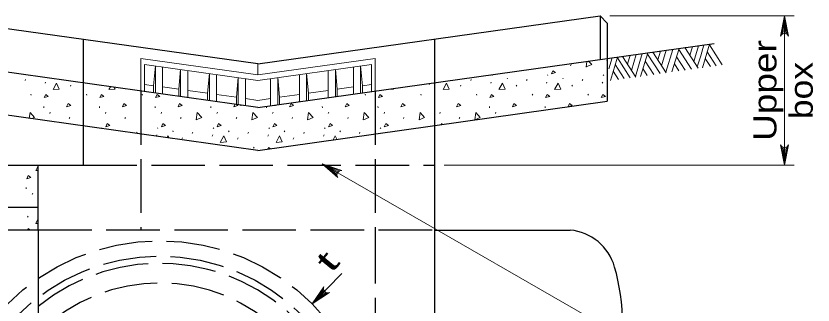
# Model space of a CAD drawing. Extents: x 1073.4 to 1107.4, y 719.4 to 741.4.
# Drawn here: x 1078.83 to 1084.36, y 727.47 to 729.48 of the extents above; entities that cross this region are included whole.
import ezdxf
from ezdxf.enums import TextEntityAlignment as Align

# ---------------------------------------------------------------- set-up
doc = ezdxf.new("R2010")
doc.units = 0
doc.header["$LTSCALE"] = 0.062
doc.linetypes.add('LONG_DASHED', pattern=[7.5, 6, -1.5])
doc.layers.add('1', color=7, linetype='Continuous', lineweight=13)

msp = doc.modelspace()

# ---------------------------------------------------------------- linework, layer by layer
at = {"layer": '1', "lineweight": 25}
for p, q in [((1080.51042, 729.14492), (1078.149, 729.47683)), ((1080.51042, 729.14492), (1082.88425, 729.47858)), ((1082.93425, 729.42867), (1082.88425, 729.47858)), ((1082.88425, 729.47858), (1082.88425, 729.17583)), ((1082.93425, 729.42867), (1082.93425, 728.88592)), ((1081.73483, 729.317), (1081.73483, 729.01425)), ((1079.29842, 729.31525), (1079.29842, 729.0125)), ((1082.93425, 729.18283), (1083.67667, 729.28717)), ((1080.51042, 728.84217), (1078.0865, 729.18283)), ((1080.51042, 728.84217), (1082.93425, 729.18283)), ((1080.51042, 728.54525), (1078.0865, 728.88592)), ((1080.51042, 728.54525), (1082.93425, 728.88592)), ((1079.29842, 728.71567), (1079.29842, 728.4425)), ((1081.73483, 728.71742), (1081.73483, 723.54533)), ((1077.93658, 728.4425), (1078.98608, 728.4425)), ((1078.98608, 728.4425), (1079.29842, 728.4425)), ((1078.98608, 727.99275), (1078.98608, 728.4425)), ((1078.10517, 728.15183), (1078.98483, 728.15183)), ((1077.93658, 727.99275), (1078.98608, 727.99275)), ((1078.98608, 727.99275), (1078.98608, 724.04508)), ((1081.73483, 727.99225), (1082.67692, 727.99225))]:
    msp.add_line(p, q, dxfattribs=at)
at = {"layer": '1'}
for p, q in [((1082.95092, 729.47858), (1084.231, 729.47858)), ((1084.1445, 729.34883), (1084.16433, 729.47858)), ((1084.15283, 729.35375), (1084.16433, 729.47858)), ((1084.16433, 729.47858), (1084.16433, 728.4425)), ((1084.16433, 729.35608), (1084.16433, 729.47858)), ((1084.17342, 729.35475), (1084.16433, 729.47858)), ((1084.18225, 729.35042), (1084.16433, 729.47858)), ((1083.50717, 729.20367), (1083.52558, 729.26592)), ((1083.53392, 729.16233), (1083.5675, 729.27183)), ((1083.58217, 729.20108), (1083.605, 729.27708)), ((1083.59375, 729.11925), (1083.64308, 729.28242)), ((1083.73175, 729.13875), (1083.64242, 729.2775)), ((1083.10208, 729.10008), (1083.13542, 729.21108)), ((1083.12883, 729.05875), (1083.17692, 729.21692)), ((1083.16408, 729.05892), (1083.21442, 729.22217)), ((1083.30017, 729.07808), (1083.21217, 729.21408)), ((1083.34258, 729.084), (1083.25025, 729.22708)), ((1083.28533, 729.17442), (1083.303, 729.23467)), ((1083.31142, 729.1325), (1083.34383, 729.24042)), ((1083.34, 729.088), (1083.38808, 729.24658)), ((1083.38258, 729.08958), (1083.43242, 729.25283)), ((1083.51858, 729.10875), (1083.43008, 729.24517)), ((1083.56433, 729.11508), (1083.47183, 729.25842)), ((1083.68992, 729.13275), (1083.62767, 729.23017)), ((1079.69825, 729.18342), (1079.69825, 728.95633)), ((1079.69825, 729.18342), (1080.51042, 729.06925)), ((1081.3225, 729.18342), (1080.51042, 729.06925)), ((1081.3225, 729.18342), (1081.3225, 728.95633)), ((1082.78758, 729.12383), (1082.793, 729.163)), ((1082.88567, 729.1755), (1082.88558, 729.176)), ((1082.93125, 729.16942), (1082.93425, 729.17617)), ((1082.94433, 729.11142), (1082.96708, 729.18742)), ((1082.95575, 729.02967), (1083.00525, 729.19283)), ((1083.09375, 729.04908), (1083.00442, 729.18783)), ((1083.13183, 729.05442), (1083.03933, 729.19808)), ((1083.07417, 729.14333), (1083.09275, 729.20508)), ((1083.2565, 729.07192), (1083.19683, 729.16483)), ((1083.47483, 729.10258), (1083.41475, 729.19558)), ((1083.55875, 729.12408), (1083.58217, 729.20108)), ((1083.64942, 729.12708), (1083.61333, 729.18375)), ((1079.72325, 729.142), (1080.51042, 729.03133)), ((1079.72325, 729.142), (1079.72325, 728.95275)), ((1079.78592, 728.99442), (1079.79817, 729.13142)), ((1079.79817, 729.13142), (1079.79817, 728.94225)), ((1079.84817, 729.12442), (1079.84817, 728.93525)), ((1079.96083, 728.96983), (1079.97308, 729.10683)), ((1079.97308, 729.10683), (1079.97308, 728.91767)), ((1080.02308, 729.09975), (1080.02308, 728.96367)), ((1080.51042, 729.06925), (1080.51042, 729.14492)), ((1081.29758, 729.142), (1080.51042, 729.03133)), ((1080.99775, 729.09975), (1080.99775, 728.96367)), ((1081.04767, 729.10683), (1081.04767, 728.91767)), ((1081.05992, 728.96983), (1081.04767, 729.10683)), ((1081.17258, 729.12442), (1081.17258, 728.93525)), ((1081.22258, 729.13142), (1081.22258, 728.94225)), ((1081.23483, 728.99442), (1081.22258, 729.13142)), ((1081.29758, 729.142), (1081.29758, 728.95275)), ((1082.67958, 729.133), (1082.68317, 729.141)), ((1083.05183, 729.04308), (1082.98975, 729.14067)), ((1083.21175, 729.06558), (1083.18117, 729.11375)), ((1083.43158, 729.0965), (1083.39983, 729.14592)), ((1080.16075, 728.94175), (1080.17308, 729.07875)), ((1080.17308, 729.07875), (1080.17308, 728.8895)), ((1080.223, 729.07175), (1080.223, 728.8825)), ((1080.36067, 728.91367), (1080.37292, 729.05067)), ((1080.37292, 729.05067), (1080.37292, 728.86142)), ((1080.42292, 729.04358), (1080.42292, 728.85442)), ((1080.59792, 729.04358), (1080.59792, 728.85442)), ((1080.64783, 729.05067), (1080.64783, 728.86142)), ((1080.66008, 728.91367), (1080.64783, 729.05067)), ((1080.79775, 729.07175), (1080.79775, 728.8825)), ((1080.84775, 729.07875), (1080.84775, 728.8895)), ((1080.86008, 728.94175), (1080.84775, 729.07875)), ((1082.13242, 729.07008), (1082.136, 729.06475)), ((1082.23875, 729.04742), (1082.24225, 729.04208)), ((1082.519, 729.07008), (1082.5225, 729.06475)), ((1082.62533, 729.04742), (1082.62883, 729.04208)), ((1082.9055, 729.07008), (1082.90908, 729.06475)), ((1082.93308, 729.07625), (1082.93425, 729.07875)), ((1082.93425, 729.07667), (1082.93308, 729.07625)), ((1083.01142, 729.03742), (1082.97542, 729.094)), ((1078.8945, 729.03008), (1078.89808, 729.03808)), ((1079.033, 729.0115), (1079.0365, 729.0195)), ((1079.20917, 728.99108), (1079.21275, 728.99908)), ((1079.47592, 728.96708), (1079.486, 728.98608)), ((1079.78592, 728.99442), (1079.72325, 729.00325)), ((1079.78592, 728.99442), (1079.78592, 728.944)), ((1079.96083, 728.96975), (1079.84817, 728.98567)), ((1081.05992, 728.96975), (1081.17258, 728.98567)), ((1081.23483, 728.99442), (1081.29758, 729.00325)), ((1081.23483, 728.99442), (1081.23483, 728.944)), ((1081.69992, 729.002), (1081.69867, 729.00917)), ((1081.73908, 729.0115), (1081.74058, 729.01508)), ((1081.91525, 728.99108), (1081.91883, 728.99908)), ((1081.98717, 729.03008), (1081.99075, 729.03808)), ((1082.12567, 729.0115), (1082.12925, 729.0195)), ((1082.30192, 728.99108), (1082.30542, 728.99908)), ((1082.37375, 729.03008), (1082.37733, 729.03808)), ((1082.51225, 729.0115), (1082.51575, 729.0195)), ((1082.68842, 728.99108), (1082.69208, 728.99908)), ((1082.76033, 729.03008), (1082.76392, 729.03808)), ((1082.89875, 729.0115), (1082.90242, 729.0195)), ((1078.9335, 728.93433), (1078.93708, 728.929)), ((1079.32017, 728.93433), (1079.32375, 728.929)), ((1079.70675, 728.93433), (1079.71025, 728.929)), ((1079.96083, 728.96983), (1079.96083, 728.91942)), ((1080.02308, 728.96108), (1080.02308, 728.91067)), ((1080.16075, 728.94175), (1080.02308, 728.96108)), ((1080.16075, 728.94175), (1080.16075, 728.89125)), ((1080.36067, 728.91358), (1080.223, 728.933)), ((1080.66008, 728.91358), (1080.79775, 728.933)), ((1080.86008, 728.94175), (1080.99775, 728.96108)), ((1080.86008, 728.94175), (1080.86008, 728.89125)), ((1080.99775, 728.96108), (1080.99775, 728.91067)), ((1081.05992, 728.96983), (1081.05992, 728.91942)), ((1081.25308, 728.93433), (1081.25667, 728.929)), ((1081.40892, 728.96708), (1081.40967, 728.9685)), ((1081.63967, 728.93433), (1081.64317, 728.929)), ((1082.02625, 728.93433), (1082.02975, 728.929)), ((1082.41283, 728.93433), (1082.41642, 728.929)), ((1082.79942, 728.93433), (1082.803, 728.929)), ((1080.36067, 728.91367), (1080.36067, 728.86308)), ((1080.51042, 728.89258), (1080.42292, 728.90483)), ((1080.51042, 728.89258), (1080.59792, 728.90483)), ((1080.66008, 728.91367), (1080.66008, 728.86308)), ((1079.02333, 728.84908), (1079.02417, 728.84125)), ((1079.40983, 728.84908), (1079.41075, 728.84125)), ((1079.79642, 728.84908), (1079.79733, 728.84125)), ((1080.183, 728.84908), (1080.18392, 728.84125)), ((1080.34242, 728.84783), (1080.3505, 728.86458)), ((1080.39075, 728.85342), (1080.38825, 728.85933)), ((1080.56967, 728.84908), (1080.5705, 728.84125)), ((1080.63, 728.85342), (1080.6325, 728.85933)), ((1080.95617, 728.84908), (1080.95708, 728.84125)), ((1081.34275, 728.84908), (1081.34367, 728.84125)), ((1082.116, 728.84908), (1082.11683, 728.84125)), ((1082.50258, 728.84908), (1082.50342, 728.84125)), ((1079.06542, 728.80208), (1079.06892, 728.81008)), ((1079.20025, 728.76567), (1079.20383, 728.77367)), ((1079.452, 728.80208), (1079.45558, 728.81008)), ((1079.58692, 728.76567), (1079.59042, 728.77367)), ((1079.83858, 728.80208), (1079.84208, 728.81008)), ((1079.97342, 728.76567), (1079.97708, 728.77367)), ((1080.22508, 728.80208), (1080.22875, 728.81008)), ((1080.36008, 728.76567), (1080.36358, 728.77367)), ((1080.61175, 728.80208), (1080.61525, 728.81008)), ((1080.74658, 728.76567), (1080.75017, 728.77367)), ((1080.99842, 728.80208), (1081.00192, 728.81008)), ((1081.13325, 728.76567), (1081.13675, 728.77367)), ((1081.38492, 728.80208), (1081.38842, 728.81008)), ((1081.51983, 728.76567), (1081.52342, 728.77367)), ((1081.7715, 728.80208), (1081.77508, 728.81008)), ((1081.90642, 728.76567), (1081.91, 728.77367)), ((1082.15808, 728.80208), (1082.16158, 728.81008)), ((1079.42625, 728.70275), (1079.42983, 728.69742)), ((1079.66808, 728.66367), (1079.67117, 728.67075)), ((1079.80608, 728.64417), (1079.80967, 728.65217)), ((1079.81283, 728.70275), (1079.81642, 728.69742)), ((1079.91917, 728.68008), (1079.92275, 728.67475)), ((1080.05425, 728.66275), (1080.05775, 728.67075)), ((1080.19275, 728.64417), (1080.19625, 728.65217)), ((1080.19942, 728.70275), (1080.203, 728.69742)), ((1080.30575, 728.68008), (1080.30942, 728.67475)), ((1080.44083, 728.66275), (1080.44442, 728.67075)), ((1080.57933, 728.64417), (1080.58283, 728.65217)), ((1080.58608, 728.70275), (1080.58958, 728.69742)), ((1080.69242, 728.68008), (1080.69592, 728.67475)), ((1080.82742, 728.66275), (1080.831, 728.67075)), ((1080.96592, 728.64417), (1080.96942, 728.65217)), ((1080.97267, 728.70275), (1080.97617, 728.69742)), ((1081.07892, 728.68008), (1081.0825, 728.67475)), ((1081.214, 728.66275), (1081.21758, 728.67075)), ((1081.35917, 728.70275), (1081.36275, 728.69742)), ((1081.4655, 728.68008), (1081.46592, 728.67958)), ((1079.98242, 728.62375), (1079.98592, 728.63175)), ((1080.1205, 728.60008), (1080.12058, 728.60008)), ((1080.36892, 728.62375), (1080.3725, 728.63175)), ((1080.7555, 728.62375), (1080.75908, 728.63175)), ((1080.90025, 728.60008), (1080.90017, 728.60008)), ((1080.47983, 728.567), (1080.48342, 728.56167)), ((1084.14642, 728.57075), (1084.16433, 728.4425)), ((1084.15525, 728.56642), (1084.16433, 728.4425)), ((1084.18417, 728.57225), (1084.16433, 728.4425)), ((1084.17583, 728.56733), (1084.16433, 728.4425)), ((1084.16433, 728.56508), (1084.16433, 728.4425)), ((1078.96792, 728.40442), (1078.98608, 728.43875)), ((1081.06267, 728.38992), (1080.95642, 728.45108)), ((1081.05883, 728.37875), (1080.95642, 728.45108)), ((1081.059, 728.36908), (1080.95642, 728.45108)), ((1081.06833, 728.39708), (1080.95642, 728.45108)), ((1081.0765, 728.40267), (1080.95642, 728.45108)), ((1081.80142, 728.4425), (1084.231, 728.4425)), ((1078.98608, 728.40592), (1078.96883, 728.40442)), ((1078.90192, 728.28642), (1078.90275, 728.2785)), ((1078.944, 728.23942), (1078.9475, 728.24742)), ((1078.9115, 728.0815), (1078.91508, 728.0895)), ((1078.96792, 728.03717), (1078.98608, 728.07142)), ((1078.98608, 728.03858), (1078.96883, 728.03717)), ((1081.09175, 727.68933), (1080.88525, 727.4805)), ((1080.96575, 727.58183), (1080.88525, 727.4805)), ((1080.96875, 727.57242), (1080.88525, 727.4805)), ((1080.97408, 727.56492), (1080.88525, 727.4805)), ((1080.98367, 727.55808), (1080.88525, 727.4805)), ((1080.99292, 727.5555), (1080.88525, 727.4805))]:
    msp.add_line(p, q, dxfattribs=at)
at = {"layer": '1', "linetype": 'LONG_DASHED', "lineweight": 25}
for p, q in [((1079.29842, 729.0125), (1079.29842, 728.71567)), ((1081.73483, 729.01425), (1081.73483, 728.71742)), ((1079.69825, 728.95633), (1079.69825, 727.99275)), ((1081.3225, 728.95633), (1081.3225, 727.99275)), ((1079.29842, 728.4425), (1081.73483, 728.4425)), ((1078.98608, 727.99275), (1081.73483, 727.99275)), ((1081.3225, 727.99275), (1081.3225, 724.04508))]:
    msp.add_line(p, q, dxfattribs=at)
at = {"layer": '1'}
for points in [[(1084.13608, 729.337), (1084.16433, 729.47858), (1084.19267, 729.337)], [(1082.80425, 729.16458), (1082.82642, 729.14175), (1082.78842, 729.12408)], [(1079.08933, 728.96708), (1079.11333, 729.01242), (1079.132, 728.97067), (1079.09025, 728.96708)], [(1081.79542, 728.96708), (1081.81942, 729.01242), (1081.83808, 728.97067), (1081.79642, 728.96708)], [(1082.18208, 728.96708), (1082.206, 729.01242), (1082.22467, 728.97067), (1082.18292, 728.96708)], [(1082.56867, 728.96708), (1082.59258, 729.01242), (1082.61125, 728.97067), (1082.56958, 728.96708)], [(1079.51333, 728.98225), (1079.5185, 728.97067), (1079.47675, 728.96708)], [(1081.44992, 728.97417), (1081.4515, 728.97067), (1081.40975, 728.96708)], [(1080.3625, 728.86292), (1080.37083, 728.85667), (1080.34242, 728.84783)], [(1078.92333, 728.76833), (1078.92875, 728.80725), (1078.9605, 728.77442), (1078.94175, 728.76575)], [(1080.08142, 728.7565), (1080.0885, 728.80725), (1080.12033, 728.77442), (1080.08225, 728.75675)], [(1080.46808, 728.7565), (1080.47508, 728.80725), (1080.50683, 728.77442), (1080.46883, 728.75675)], [(1080.85467, 728.7565), (1080.86175, 728.80725), (1080.89342, 728.77442), (1080.8555, 728.75675)], [(1081.24125, 728.7565), (1081.24825, 728.80725), (1081.28008, 728.77442), (1081.24208, 728.75675)], [(1081.62775, 728.7565), (1081.63483, 728.80725), (1081.66667, 728.77442), (1081.62867, 728.75675)], [(1082.01442, 728.75667), (1082.02142, 728.80725), (1082.05317, 728.77442), (1082.01525, 728.75675)], [(1081.78042, 728.72375), (1081.78392, 728.73108), (1081.79158, 728.72542)], [(1079.8805, 728.63375), (1079.8865, 728.64508), (1079.89233, 728.63208)], [(1080.24908, 728.59983), (1080.27308, 728.64508), (1080.29175, 728.60342), (1080.25, 728.59983)], [(1080.63575, 728.59983), (1080.65967, 728.64508), (1080.67833, 728.60342), (1080.63658, 728.59983)], [(1081.03217, 728.61858), (1081.04625, 728.64508), (1081.0565, 728.622)], [(1080.57833, 728.55475), (1080.58375, 728.56608), (1080.59558, 728.55725)], [(1084.19267, 728.58408), (1084.16433, 728.4425), (1084.13608, 728.58408)], [(1081.06508, 728.35583), (1080.95642, 728.45108), (1081.09333, 728.40492)], [(1080.95642, 728.45108), (1083.35958, 727.06742), (1083.49042, 727.06742)], [(1078.91083, 727.99275), (1078.91592, 728.00342), (1078.93017, 727.99275)], [(1081.00742, 727.5575), (1080.88525, 727.4805), (1080.96842, 727.59858)]]:
    msp.add_lwpolyline(points, dxfattribs=at)
for points in [[(1082.54642, 729.07625), (1082.55708, 729.09842), (1082.57492, 729.08508)], [(1079.02675, 728.91125), (1079.03742, 728.93342), (1079.05508, 728.92008)], [(1079.41333, 728.91125), (1079.424, 728.93342), (1079.44175, 728.92008)], [(1079.79992, 728.91125), (1079.81058, 728.93342), (1079.82833, 728.92008)], [(1081.34625, 728.91125), (1081.35692, 728.93342), (1081.37467, 728.92008)], [(1082.11942, 728.91125), (1082.13008, 728.93342), (1082.14783, 728.92008)], [(1082.50608, 728.91125), (1082.51667, 728.93342), (1082.53442, 728.92008)], [(1082.89258, 728.91125), (1082.90325, 728.93342), (1082.921, 728.92008)], [(1079.18275, 728.84783), (1079.19333, 728.87), (1079.21108, 728.85667)], [(1079.56933, 728.84783), (1079.58, 728.87), (1079.59775, 728.85667)], [(1079.95592, 728.84783), (1079.9665, 728.87), (1079.98433, 728.85667)], [(1080.72908, 728.84783), (1080.73975, 728.87), (1080.75742, 728.85667)], [(1081.11567, 728.84783), (1081.12633, 728.87), (1081.14408, 728.85667)], [(1081.50225, 728.84783), (1081.51292, 728.87), (1081.53067, 728.85667)], [(1081.88875, 728.84783), (1081.89942, 728.87), (1081.91725, 728.85667)], [(1082.27542, 728.84783), (1082.28608, 728.87), (1082.30375, 728.85667)], [(1082.66208, 728.84783), (1082.67267, 728.87), (1082.69042, 728.85667)], [(1079.45375, 728.70892), (1079.46442, 728.73108), (1079.48208, 728.71775)], [(1079.84033, 728.70892), (1079.851, 728.73108), (1079.86875, 728.71775)], [(1080.22692, 728.70892), (1080.23758, 728.73108), (1080.25533, 728.71775)], [(1080.61342, 728.70892), (1080.62408, 728.73108), (1080.64192, 728.71775)], [(1081.00008, 728.70892), (1081.01075, 728.73108), (1081.0285, 728.71775)], [(1081.38675, 728.70892), (1081.39742, 728.73108), (1081.41508, 728.71775)], [(1078.90542, 728.34858), (1078.91592, 728.37075), (1078.93375, 728.35742)]]:
    msp.add_lwpolyline(points, close=True, dxfattribs=at)
for centre, start, end in [((1084.16437, 729.32555), 22.08782, 157.91395), ((1084.16431, 728.59555), 202.08782, 337.91395), ((1081.0891, 728.37471), 82.1568, 217.98293), ((1080.99614, 727.58597), 155.62115, 291.44728)]:
    msp.add_arc(centre, 0.03056, start, end, dxfattribs=at)
at = {"layer": '1', "lineweight": 25}
for centre, major_axis, ratio, start_param, end_param in [((1082.64334, 727.63919), (0.35468, 0), 0.999895, 0.2744611, 1.4760278), ((1082.13992, 726.52595), (-0.53831, -1.59536), 0.454237, 1.2862985, 2.5699002)]:
    msp.add_ellipse(centre, major_axis=major_axis, ratio=ratio, start_param=start_param, end_param=end_param, dxfattribs=at)
at = {"layer": '1', "linetype": 'LONG_DASHED', "lineweight": 25}
for centre, major_axis in [((1079.82948, 726.42488), (1.49306, 0)), ((1079.82951, 726.42488), (1.38685, 0))]:
    msp.add_ellipse(centre, major_axis=major_axis, ratio=0.999895, dxfattribs=at)
for major_axis, start_param, end_param in [((1.33687, 0), 4.0297001, 8.5366706), ((1.19944, 0), 3.93253, 8.6338407)]:
    msp.add_ellipse((1079.82951, 726.42488), major_axis=major_axis, ratio=0.999895, start_param=start_param, end_param=end_param, dxfattribs=at)

# ---------------------------------------------------------------- texts
at = {"layer": '1'}
for s, width, p in [('Upper', 1.2, (1084.10792, 728.9605)), ('box', 1.15, (1084.35967, 728.96054))]:
    msp.add_text(s, height=0.16, rotation=90, dxfattribs=dict(at, width=width)).set_placement(p, align=Align.CENTER)
at = {"layer": '1', "width": 1.75}
msp.add_text('t', height=0.16, rotation=50.676, dxfattribs=at).set_placement((1081.02008, 727.68342))

doc.saveas('drawing.dxf')
